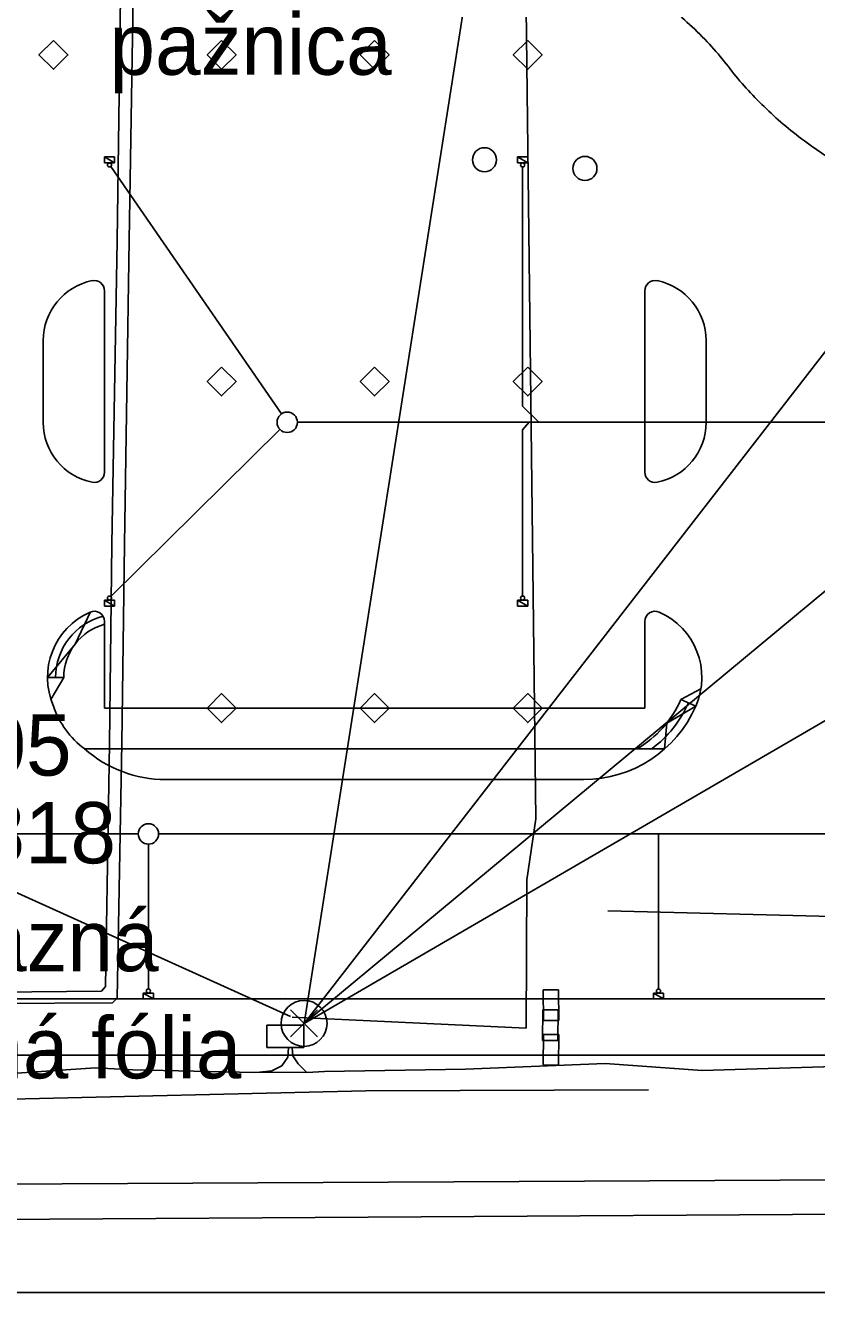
# Model space of a CAD drawing. Extents: x -264090 to -263500, y -1242327 to -1242030.
# Drawn here: x -263959.9 to -263921.2, y -1242326.6 to -1242264.5 of the extents above; entities that cross this region are included whole.
import ezdxf

# ---------------------------------------------------------------- set-up
doc = ezdxf.new("R2010")
doc.units = 0
for name, color, linetype in [('KFA_KOORD_SIT_a_IS_SEDA', 7, 'Continuous'), ('KFA_ZVS_BOD_CISLO', 7, 'Continuous'), ('KFA_ZVS_BOD_SYMBOL', 7, 'Continuous'), ('KFA_ZVS_BOD_VYSKA', 7, 'Continuous'), ('KFA_ZVS_NIVELACIA', 7, 'Continuous'), ('KFA_ZVS_POPIS', 7, 'Continuous'), ('KFA_ZVS_SMERY_A_DLZKY', 7, 'Continuous'), ('RAM_NA_TLAC', 7, 'Continuous')]:
    doc.layers.add(name, color=color, linetype=linetype)

msp = doc.modelspace()

# ---------------------------------------------------------------- linework, layer by layer
at = {"layer": 'KFA_KOORD_SIT_a_IS_SEDA'}
for p, q in [((-263955.442, -1242275.089), (-263955.264, -1242261.849)), ((-263954.644, -1242261.82), (-263954.858, -1242275.059)), ((-263935.392, -1242263.705), (-263934.919, -1242303.408)), ((-263956.068, -1242270.982), (-263955.568, -1242270.982)), ((-263956.068, -1242271.272), (-263956.068, -1242270.982)), ((-263956.068, -1242270.982), (-263955.568, -1242271.272)), ((-263956.068, -1242270.982), (-263955.568, -1242271.272)), ((-263955.568, -1242270.982), (-263956.068, -1242270.982)), ((-263955.568, -1242270.982), (-263955.568, -1242271.272)), ((-263955.568, -1242271.272), (-263955.568, -1242270.982)), ((-263935.824, -1242270.983), (-263935.324, -1242270.983)), ((-263935.824, -1242271.273), (-263935.824, -1242270.983)), ((-263935.824, -1242270.983), (-263935.324, -1242271.273)), ((-263935.824, -1242270.983), (-263935.324, -1242271.273)), ((-263935.324, -1242270.983), (-263935.824, -1242270.983)), ((-263935.324, -1242270.983), (-263935.324, -1242271.273)), ((-263935.324, -1242271.273), (-263935.324, -1242270.983)), ((-263955.568, -1242271.272), (-263956.068, -1242271.272)), ((-263955.761, -1242271.455), (-263947.392, -1242283.571)), ((-263935.324, -1242271.273), (-263935.824, -1242271.273)), ((-263935.574, -1242271.473), (-263935.574, -1242283.187)), ((-263955.703, -1242289.949), (-263955.442, -1242275.089)), ((-263954.858, -1242275.059), (-263955.079, -1242289.952)), ((-263956.068, -1242286.432), (-263956.068, -1242277.533)), ((-263929.58, -1242286.432), (-263929.58, -1242277.533)), ((-263959.068, -1242279.982), (-263959.068, -1242283.982)), ((-263926.58, -1242283.982), (-263926.58, -1242279.982)), ((-263926.58, -1242280.482), (-263926.58, -1242283.982)), ((-263935.574, -1242283.187), (-263934.779, -1242283.982)), ((-263946.608, -1242283.982), (-263908.955, -1242283.982)), ((-263946.608, -1242283.982), (-263904.413, -1242283.982)), ((-263935.574, -1242284.343), (-263935.249, -1242283.982)), ((-263955.747, -1242292.522), (-263947.464, -1242284.334)), ((-263935.574, -1242292.492), (-263935.574, -1242284.343)), ((-263955.703, -1242289.949), (-263955.826, -1242299.741)), ((-263955.217, -1242299.695), (-263955.079, -1242289.952)), ((-263956.068, -1242292.692), (-263955.568, -1242292.692)), ((-263956.068, -1242292.982), (-263956.068, -1242292.692)), ((-263956.068, -1242292.692), (-263955.568, -1242292.982)), ((-263956.068, -1242292.692), (-263955.568, -1242292.982)), ((-263955.568, -1242292.692), (-263956.068, -1242292.692)), ((-263955.568, -1242292.692), (-263955.568, -1242292.982)), ((-263955.568, -1242292.982), (-263955.568, -1242292.692)), ((-263935.824, -1242292.692), (-263935.324, -1242292.692)), ((-263935.824, -1242292.982), (-263935.824, -1242292.692)), ((-263935.824, -1242292.692), (-263935.324, -1242292.982)), ((-263935.824, -1242292.692), (-263935.324, -1242292.982)), ((-263935.324, -1242292.692), (-263935.824, -1242292.692)), ((-263935.324, -1242292.692), (-263935.324, -1242292.982)), ((-263935.324, -1242292.982), (-263935.324, -1242292.692)), ((-263955.568, -1242292.982), (-263956.068, -1242292.982)), ((-263935.324, -1242292.982), (-263935.824, -1242292.982)), ((-263956.068, -1242297.982), (-263956.068, -1242293.737)), ((-263929.58, -1242297.982), (-263929.58, -1242293.737)), ((-263927.814, -1242297.562), (-263926.833, -1242297.035)), ((-263927.814, -1242297.562), (-263927.081, -1242297.882)), ((-263929.58, -1242297.982), (-263956.068, -1242297.982)), ((-263955.826, -1242299.741), (-263956.021, -1242311.627)), ((-263955.441, -1242312.2), (-263955.217, -1242299.695)), ((-263928.612, -1242299.982), (-263957.036, -1242299.982)), ((-263932.58, -1242301.482), (-263953.068, -1242301.482)), ((-263934.919, -1242303.408), (-263935.359, -1242306.39)), ((-263954.413, -1242304.147), (-264003.396, -1242304.147)), ((-263946.956, -1242313.086), (-263966.621, -1242304.217)), ((-263953.913, -1242311.742), (-263953.913, -1242304.647)), ((-263904.413, -1242304.147), (-263953.413, -1242304.147)), ((-263928.913, -1242311.742), (-263928.913, -1242304.147)), ((-263935.359, -1242306.39), (-263935.397, -1242313.657)), ((-263901.294, -1242308.658), (-263931.403, -1242307.918)), ((-263956.215, -1242311.842), (-263967.857, -1242311.986)), ((-263956.021, -1242311.627), (-263956.215, -1242311.842)), ((-263955.668, -1242312.416), (-263955.441, -1242312.2)), ((-263954.163, -1242311.942), (-263953.663, -1242311.942)), ((-263954.163, -1242312.232), (-263954.163, -1242311.942)), ((-263954.163, -1242311.942), (-263953.663, -1242312.232)), ((-263954.163, -1242311.942), (-263953.663, -1242312.232)), ((-263953.663, -1242311.942), (-263954.163, -1242311.942)), ((-263953.663, -1242311.942), (-263953.663, -1242312.232)), ((-263953.663, -1242312.232), (-263953.663, -1242311.942)), ((-263947.211, -1242311.99), (-263947.211, -1242311.99)), ((-263934.558, -1242311.787), (-263933.808, -1242311.785)), ((-263934.552, -1242313.287), (-263934.558, -1242311.787)), ((-263933.808, -1242311.785), (-263933.802, -1242313.285)), ((-263929.163, -1242311.942), (-263928.663, -1242311.942)), ((-263929.163, -1242312.232), (-263929.163, -1242311.942)), ((-263929.163, -1242311.942), (-263928.663, -1242312.232)), ((-263929.163, -1242311.942), (-263928.663, -1242312.232)), ((-263928.663, -1242311.942), (-263929.163, -1242311.942)), ((-263928.663, -1242311.942), (-263928.663, -1242312.232)), ((-263928.663, -1242312.232), (-263928.663, -1242311.942)), ((-263980.94, -1242312.232), (-263857.327, -1242312.232)), ((-263967.842, -1242312.514), (-263955.668, -1242312.416)), ((-263953.663, -1242312.232), (-263954.163, -1242312.232)), ((-263934.592, -1242314.26), (-263934.578, -1242312.761)), ((-263934.578, -1242312.761), (-263933.828, -1242312.768)), ((-263933.828, -1242312.768), (-263933.842, -1242314.267)), ((-263928.663, -1242312.232), (-263929.163, -1242312.232)), ((-263842.601, -1242312.24), (-263924.192, -1242312.232)), ((-263935.397, -1242313.657), (-263946.874, -1242313.117)), ((-263933.802, -1242313.285), (-263934.552, -1242313.287)), ((-263934.552, -1242313.287), (-263934.552, -1242313.287)), ((-263946.29, -1242313.51), (-263948.11, -1242313.51)), ((-263948.11, -1242313.51), (-263948.11, -1242314.61)), ((-263946.29, -1242314.61), (-263946.29, -1242313.51)), ((-263934.558, -1242315.465), (-263934.55, -1242313.965)), ((-263934.55, -1242313.965), (-263933.8, -1242313.969)), ((-263933.8, -1242313.969), (-263933.808, -1242315.469)), ((-263948.11, -1242314.61), (-263946.29, -1242314.61)), ((-263947.08, -1242315.09), (-263947.04, -1242314.61)), ((-263946.86, -1242314.61), (-263946.83, -1242315.01)), ((-263933.842, -1242314.267), (-263934.592, -1242314.26)), ((-263934.592, -1242314.26), (-263934.592, -1242314.26)), ((-264038.443, -1242314.982), (-263836.403, -1242314.982)), ((-263947.37, -1242315.51), (-263947.08, -1242315.09)), ((-263946.83, -1242315.01), (-263946.58, -1242315.41)), ((-263963.59, -1242316.09), (-263956.5, -1242315.61)), ((-263956.5, -1242315.61), (-263954.68, -1242315.7)), ((-263954.68, -1242315.7), (-263948.7, -1242315.83)), ((-263948.7, -1242315.83), (-263948.46, -1242315.82)), ((-263948.46, -1242315.82), (-263947.86, -1242315.75)), ((-263948.46, -1242315.82), (-263946.15, -1242315.83)), ((-263947.86, -1242315.75), (-263947.37, -1242315.51)), ((-263946.58, -1242315.41), (-263946.15, -1242315.83)), ((-263946.15, -1242315.83), (-263945.29, -1242315.78)), ((-263945.29, -1242315.78), (-263938.38, -1242315.67)), ((-263938.38, -1242315.67), (-263931.52, -1242315.4)), ((-263933.808, -1242315.469), (-263934.558, -1242315.465)), ((-263934.558, -1242315.465), (-263934.558, -1242315.465)), ((-263931.52, -1242315.4), (-263926.77, -1242315.74)), ((-263926.77, -1242315.74), (-263919.34, -1242315.51)), ((-263963.871, -1242317.222), (-263943.249, -1242316.734)), ((-263943.249, -1242316.734), (-263929.405, -1242316.676)), ((-263961.846, -1242321.299), (-263870.439, -1242320.864)), ((-263976.89, -1242323.14), (-263880.39, -1242322.51))]:
    msp.add_line(p, q, dxfattribs=at)
for points in [[(-263958.568, -1242265.275), (-263957.861, -1242265.982), (-263958.568, -1242266.689), (-263959.275, -1242265.982)], [(-263950.324, -1242265.275), (-263949.617, -1242265.982), (-263950.324, -1242266.689), (-263951.031, -1242265.982)], [(-263942.824, -1242265.275), (-263942.117, -1242265.982), (-263942.824, -1242266.689), (-263943.531, -1242265.982)], [(-263935.324, -1242265.275), (-263934.617, -1242265.982), (-263935.324, -1242266.689), (-263936.031, -1242265.982)], [(-263950.324, -1242281.275), (-263949.617, -1242281.982), (-263950.324, -1242282.689), (-263951.031, -1242281.982)], [(-263942.824, -1242281.275), (-263942.117, -1242281.982), (-263942.824, -1242282.689), (-263943.531, -1242281.982)], [(-263935.324, -1242281.275), (-263934.617, -1242281.982), (-263935.324, -1242282.689), (-263936.031, -1242281.982)], [(-263949.617, -1242297.982), (-263950.324, -1242297.275), (-263951.031, -1242297.982), (-263950.324, -1242298.689)], [(-263942.117, -1242297.982), (-263942.824, -1242297.275), (-263943.531, -1242297.982), (-263942.824, -1242298.689)], [(-263934.617, -1242297.982), (-263935.324, -1242297.275), (-263936.031, -1242297.982), (-263935.324, -1242298.689)]]:
    msp.add_lwpolyline(points, close=True, dxfattribs=at)
for points in [[(-263958.859, -1242296.482), (-263957.504, -1242294.843), (-263956.756, -1242293.273)], [(-263958.859, -1242296.482), (-263958.059, -1242296.482), (-263958.688, -1242297.562)], [(-263927.081, -1242297.882), (-263928.506, -1242298.713), (-263928.612, -1242299.982)]]:
    msp.add_lwpolyline(points, dxfattribs=at)
for centre, radius in [((-263937.442, -1242271.12), 0.59), ((-263932.518, -1242271.545), 0.59), ((-263955.818, -1242271.373), 0.1), ((-263935.574, -1242271.373), 0.1), ((-263947.108, -1242283.982), 0.5), ((-263955.818, -1242292.592), 0.1), ((-263935.574, -1242292.592), 0.1), ((-263953.913, -1242304.147), 0.5), ((-263953.913, -1242311.842), 0.1), ((-263928.913, -1242311.842), 0.1)]:
    msp.add_circle(centre, radius, dxfattribs=at)
for centre, radius, start, end in [((-263956.068, -1242279.982), 3, 101.53696, 180), ((-263956.568, -1242277.533), 0.5, 0, 101.53696), ((-263929.08, -1242277.533), 0.5, 78.46304, 180), ((-263929.58, -1242279.982), 3, 0, 78.46304), ((-263956.068, -1242283.982), 3, 180, 258.46304), ((-263929.58, -1242283.982), 3, 281.53696, 0), ((-263956.568, -1242286.432), 0.5, 258.46304, 0), ((-263929.08, -1242286.432), 0.5, 180, 281.53696), ((-263955.359, -1242296.482), 3.5, 113.75985, 203.57818), ((-263955.359, -1242296.482), 3.1, 104.54571, 180), ((-263956.568, -1242293.737), 0.5, 0, 113.75985), ((-263929.08, -1242293.737), 0.5, 66.24015, 180), ((-263930.289, -1242296.482), 3.5, 336.42182, 66.24015), ((-263955.359, -1242296.482), 2.7, 105.21758, 180), ((-263954.444, -1242296.485), 4.353, 198.7173, 233.45125), ((-263932.58, -1242295.482), 6, 270, 336.42182), ((-263932.58, -1242295.482), 5.2, 300.07335, 336.42182), ((-263932.58, -1242295.482), 5.6, 306.52749, 336.42182), ((-263953.068, -1242295.482), 6, 228.59038, 270)]:
    msp.add_arc(centre, radius, start, end, dxfattribs=at)
at = {"layer": 'KFA_ZVS_BOD_SYMBOL'}
for p, q in [((-263946.946, -1242314.093), (-263945.62, -1242312.767)), ((-263945.62, -1242314.093), (-263946.946, -1242312.767))]:
    msp.add_line(p, q, dxfattribs=at)
msp.add_circle((-263946.283, -1242313.43), 1.125, dxfattribs=at)
at = {"layer": 'KFA_ZVS_NIVELACIA'}
for points in [[(-263937.6, -1242258.211), (-263928.936, -1242262.063), (-263922.038, -1242271.064), (-263908.691, -1242276.165), (-263901.493, -1242267.314), (-263884.997, -1242267.314), (-263876.149, -1242269.264), (-263867.589, -1242264.788), (-263858.267, -1242262.294)], [(-263858.267, -1242262.294), (-263872.503, -1242264.923), (-263878.722, -1242267.127), (-263884.99, -1242265.854), (-263892.335, -1242262.572), (-263906.067, -1242264.914), (-263907.585, -1242268.147), (-263919.043, -1242268.147), (-263920.708, -1242262.66), (-263931.12, -1242259.749), (-263937.6, -1242258.211)]]:
    msp.add_open_spline(points, degree=2, dxfattribs=at)
at = {"layer": 'KFA_ZVS_SMERY_A_DLZKY'}
for p in [(-263779.166, -1242098.021), (-263768.002, -1242165.53), (-263937.6, -1242258.211), (-263858.267, -1242262.294)]:
    msp.add_line(p, (-263946.283, -1242313.43), dxfattribs=at)
at = {"layer": 'RAM_NA_TLAC'}
msp.add_lwpolyline([(-264089.658, -1242029.619), (-263499.658, -1242029.619), (-263499.658, -1242326.619), (-264089.658, -1242326.619)], close=True, dxfattribs=at)

# ---------------------------------------------------------------- texts
at = {"layer": 'KFA_ZVS_BOD_CISLO'}
msp.add_text('8005', height=3, dxfattribs=at).set_placement((-263966.604, -1242301.286))
at = {"layer": 'KFA_ZVS_BOD_VYSKA'}
msp.add_text('239.818', height=3, dxfattribs=at).set_placement((-263970.002, -1242305.587))
at = {"layer": 'KFA_ZVS_POPIS'}
for s, p in [('pažnica', (-263955.82, -1242266.958)), ('odrazná', (-263967.914, -1242310.871)), ('reflexná fólia', (-263972.103, -1242316.121))]:
    msp.add_text(s, height=3, dxfattribs=at).set_placement(p)

doc.saveas('drawing.dxf')
